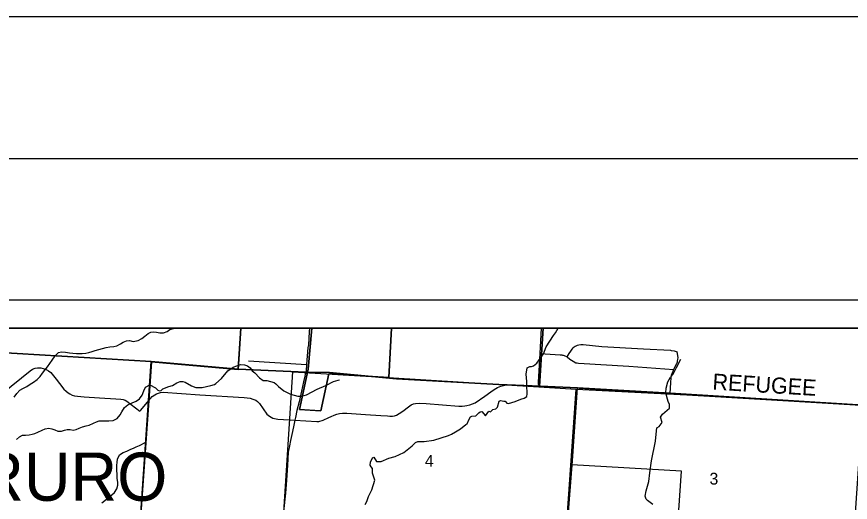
# Model space of a CAD drawing. Extents: x 0 to 34, y 0 to 22.
# Drawn here: x 3.515 to 6.46, y 20.286 to 22 of the extents above; entities that cross this region are included whole.
import ezdxf

# ---------------------------------------------------------------- set-up
doc = ezdxf.new("R2010")
doc.units = 0
for name, color, linetype in [('GM_X_City_Street', 7, 'Continuous'), ('GM_X_Corporation', 7, 'Continuous'), ('GM_X_County', 7, 'Continuous'), ('GM_X_Minor_River', 7, 'Continuous'), ('GM_X_Section_Text', 7, 'Continuous'), ('GM_X_Township_Road', 7, 'Continuous'), ('GM_X_Township_Road_Text', 7, 'Continuous'), ('GM_X_Township_Text', 7, 'Continuous'), ('SH_Border', 7, 'Continuous'), ('SH_Cut_Line', 7, 'Continuous'), ('SH_Data', 7, 'Continuous')]:
    doc.layers.add(name, color=color, linetype=linetype)

msp = doc.modelspace()

# ---------------------------------------------------------------- linework, layer by layer
at = {"layer": 'GM_X_City_Street'}
msp.add_line((4.3347, 20.7849), (4.539, 20.7724), dxfattribs=at)
for points in [[(5.4597, 20.7994), (5.4672, 20.8117), (5.4721, 20.8193), (5.4774, 20.8266), (5.4804, 20.8308), (5.485, 20.8342), (5.488, 20.8369), (5.491, 20.8384), (5.4959, 20.8407), (5.5009, 20.8422), (5.5077, 20.8427), (5.5168, 20.8427), (5.5821, 20.8358), (5.7294, 20.8277), (5.8244, 20.8231), (5.827, 20.822), (5.838, 20.8202), (5.8487, 20.8175)], [(5.824, 20.6706), (5.8262, 20.7075), (5.8275, 20.7265), (5.8287, 20.7351), (5.836, 20.7547), (5.8364, 20.756), (5.8466, 20.7757), (5.8477, 20.778), (5.8492, 20.7822), (5.8499, 20.7856), (5.8507, 20.7898), (5.8514, 20.7974), (5.8487, 20.8175)], [(5.3643, 20.8113), (5.435, 20.8066), (5.4388, 20.8063), (5.4407, 20.8063), (5.4433, 20.8055), (5.446, 20.8052), (5.4494, 20.8037), (5.4597, 20.7994), (5.4691, 20.7906), (5.4805, 20.784), (5.4905, 20.7784), (5.4935, 20.778), (5.4951, 20.7776), (5.5, 20.7769), (5.6773, 20.7663), (5.836, 20.7547)], [(4.4984, 20.5754), (4.576, 20.571), (4.5831, 20.5714), (4.5984, 20.5762), (4.6175, 20.585), (4.6262, 20.5889), (4.6365, 20.593), (4.6464, 20.5971), (4.6555, 20.5996), (4.6663, 20.6009), (4.6816, 20.6004), (4.7477, 20.5963), (4.8018, 20.5918), (4.8246, 20.5909), (4.8337, 20.5905), (4.8423, 20.5905), (4.8502, 20.5913), (4.8572, 20.5938), (4.8663, 20.5988), (4.8795, 20.6071), (4.8998, 20.6232), (4.9089, 20.6294), (4.9168, 20.6331), (4.9242, 20.6352), (4.9391, 20.636), (4.9614, 20.6347), (5.0193, 20.6294), (5.0771, 20.6252), (5.0892, 20.6253), (5.0978, 20.6259), (5.1059, 20.6272), (5.1164, 20.6302), (5.1252, 20.6332), (5.1342, 20.6373), (5.1685, 20.6606), (5.1899, 20.6756), (5.2018, 20.6841), (5.2134, 20.6916), (5.2256, 20.6963), (5.2399, 20.6998), (5.2476, 20.7), (5.3655, 20.695)], [(3.9816, 20.645), (3.9939, 20.6591), (4.0028, 20.6649), (4.0089, 20.6689), (4.0232, 20.6731), (4.0323, 20.6743), (4.1624, 20.6651), (4.3187, 20.6553), (4.3396, 20.6533), (4.3499, 20.6504), (4.3597, 20.6466), (4.3664, 20.6418), (4.3734, 20.6349), (4.3985, 20.5973), (4.4085, 20.5894), (4.4196, 20.5831), (4.438, 20.5789), (4.4984, 20.5754)]]:
    msp.add_lwpolyline(points, dxfattribs=at)
at = {"layer": 'GM_X_Corporation'}
for points in [[(4.3071, 20.9), (2.1, 20.9), (2.1, 14.1), (3.0169, 14.1), (3.0406, 14.4484), (3.1026, 15.287), (3.1745, 16.2606), (2.934, 16.2765), (2.366, 16.3159), (2.2862, 16.3208), (2.1768, 16.323), (2.2478, 17.3472), (2.3155, 18.3567), (3.8153, 18.2543), (3.8503, 18.7566), (3.8611, 18.9124), (3.8924, 19.3621), (3.9019, 19.4987), (3.9133, 19.6628), (3.9816, 20.645), (3.9912, 20.7822), (4.2975, 20.7549)], [(4.3068, 20.9), (2.1, 20.9), (2.1, 20.8993), (2.2596, 20.8916), (2.7336, 20.8606), (3.2798, 20.8248), (3.9909, 20.7828), (4.2973, 20.7554)], [(8.9, 20.4724), (8.9, 20.9), (4.3068, 20.9), (4.2973, 20.7554), (4.5367, 20.7456), (4.6201, 20.7441), (4.8574, 20.7216), (5.2396, 20.7003), (5.2473, 20.7005), (5.3653, 20.6955), (5.4957, 20.69), (5.8237, 20.6711), (6.676, 20.6183), (7.8827, 20.5405), (8.4655, 20.5021), (8.5224, 20.4984)], [(4.8398, 20.9), (4.5578, 20.9), (4.5447, 20.7555), (4.5144, 20.614), (4.5896, 20.6089), (4.6184, 20.7391), (4.8298, 20.7264)], [(8.9, 20.4697), (8.9, 20.9), (5.3755, 20.9), (5.362, 20.6955), (5.3653, 20.6955), (5.4957, 20.69), (5.5024, 20.6884), (6.6719, 20.618), (7.8826, 20.5367), (8.4626, 20.4977), (8.5169, 20.4922)], [(4.4912, 20.7461), (4.8271, 20.7263), (5.3592, 20.6938), (5.4919, 20.6855), (5.4537, 20.1473), (4.9568, 20.181), (4.9537, 20.1812), (4.4572, 20.2143)], [(5.4919, 20.6855), (5.8824, 20.6656), (6.3999, 20.6351), (6.5029, 20.629), (6.4654, 20.076), (5.9674, 20.1102), (5.4537, 20.1473)]]:
    msp.add_lwpolyline(points, close=True, dxfattribs=at)
for points in [[(3.8151, 18.2549), (3.8501, 18.7572), (3.8609, 18.9129), (3.8918, 19.3576), (3.8924, 19.3656), (3.9015, 19.4967), (3.9015, 19.497), (3.9131, 19.6633), (3.9131, 19.6638), (3.9335, 19.9563), (3.9417, 20.0742), (3.9814, 20.6455), (3.9909, 20.7828), (4.2973, 20.7554), (4.3068, 20.9), (2.1, 20.9), (2.1, 14.1)], [(3.8151, 18.2549), (3.8501, 18.7572), (3.8609, 18.9129), (3.8918, 19.3576), (3.8924, 19.3656), (3.9015, 19.4967), (3.9015, 19.497), (3.9131, 19.6633), (3.9131, 19.6638), (3.9335, 19.9563), (3.9417, 20.0742), (3.9814, 20.6455), (3.9909, 20.7828), (3.2798, 20.8248), (2.7336, 20.8606), (2.2596, 20.8916), (2.1, 20.8993), (2.1, 16.3272)], [(5.8451, 20.1209), (5.864, 20.3961), (5.4765, 20.4182), (5.4847, 20.546), (5.4957, 20.69), (5.3653, 20.6955), (5.362, 20.6955), (5.3755, 20.9), (4.8398, 20.9), (4.8298, 20.7264), (4.6184, 20.7391), (4.5896, 20.6089), (4.5863, 20.6092), (4.5144, 20.614), (4.5447, 20.7555), (4.5578, 20.9), (2.7432, 20.9)], [(8.9, 20.9), (4.3068, 20.9), (4.2973, 20.7554), (3.9909, 20.7828), (3.9814, 20.6455), (3.9417, 20.0742), (3.9335, 19.9563), (3.9131, 19.6638), (3.9131, 19.6633), (3.9015, 19.497), (3.9015, 19.4967), (3.8924, 19.3656), (3.8918, 19.3576), (3.8609, 18.9129), (3.8501, 18.7572), (3.8151, 18.2549)], [(8.9, 20.9), (4.3071, 20.9), (4.2975, 20.7549), (3.9912, 20.7822), (3.9816, 20.645), (3.9133, 19.6628), (3.9019, 19.4987), (3.8924, 19.3621), (3.8611, 18.9124), (3.8503, 18.7566), (3.8153, 18.2543), (4.1999, 18.2271), (4.3271, 18.2226), (4.5528, 18.2021), (4.7449, 18.1929), (4.9551, 18.1768), (5.5447, 18.1318), (5.8371, 18.1158), (5.9465, 18.1082), (6.0343, 18.1015), (6.0906, 18.0978), (6.5646, 18.0583)], [(6.676, 20.6183), (5.8237, 20.6711), (5.4957, 20.69), (5.3653, 20.6955), (5.2473, 20.7005), (5.2396, 20.7003), (4.8574, 20.7216), (4.6201, 20.7441), (4.5367, 20.7456), (4.2973, 20.7554), (3.9909, 20.7828), (3.9814, 20.6455), (3.9417, 20.0742), (3.9335, 19.9563), (3.9131, 19.6638), (3.9131, 19.6633), (3.9015, 19.497), (3.9015, 19.4967), (3.8924, 19.3656), (3.8918, 19.3576), (3.8609, 18.9129), (3.8501, 18.7572), (3.8151, 18.2549)]]:
    msp.add_lwpolyline(points, dxfattribs=at)
at = {"layer": 'GM_X_County'}
msp.add_lwpolyline([(3.8151, 18.2549), (3.8501, 18.7572), (3.8609, 18.9129), (3.8918, 19.3576), (3.8924, 19.3656), (3.9015, 19.4967), (3.9015, 19.497), (3.9131, 19.6633), (3.9131, 19.6638), (3.9335, 19.9563), (3.9417, 20.0742), (3.9814, 20.6455), (3.9909, 20.7828), (4.2973, 20.7554), (4.3068, 20.9)], dxfattribs=at)
at = {"layer": 'GM_X_Minor_River'}
for points in [[(3.5063, 20.6574), (3.5158, 20.6703), (3.5261, 20.6812), (3.5375, 20.688), (3.5515, 20.6943), (3.5633, 20.7026), (3.575, 20.7098), (3.5872, 20.7195), (3.5978, 20.7301), (3.607, 20.7422), (3.6146, 20.752), (3.6238, 20.7641), (3.6322, 20.7754), (3.6409, 20.7875), (3.6512, 20.803), (3.6634, 20.8147), (3.674, 20.8169), (3.6884, 20.8157), (3.7024, 20.8133), (3.7137, 20.8125), (3.7265, 20.8109), (3.7368, 20.8109), (3.7473, 20.8112), (3.7594, 20.8122), (3.77, 20.8144), (3.7818, 20.8178), (3.7928, 20.8219), (3.8053, 20.8256), (3.8189, 20.8293), (3.831, 20.8323), (3.8443, 20.8341), (3.859, 20.8359), (3.8693, 20.8385), (3.8818, 20.8453), (3.892, 20.8513), (3.9034, 20.8558), (3.9144, 20.8572), (3.9268, 20.8537), (3.9443, 20.8566), (3.9575, 20.8638), (3.9682, 20.8721), (3.9796, 20.8815), (3.9894, 20.886), (3.9997, 20.8878), (4.0095, 20.8862), (4.0212, 20.8835), (4.0341, 20.8846), (4.0466, 20.889), (4.0568, 20.8958), (4.0689, 20.8995), (4.0702, 20.9)], [(5.123, 20.5903), (5.137, 20.5911), (5.1476, 20.6013), (5.1525, 20.6055), (5.1586, 20.6066), (5.1707, 20.5906), (5.1836, 20.6081), (5.1885, 20.6054), (5.1972, 20.6138), (5.2078, 20.6156), (5.2135, 20.6221), (5.2195, 20.6429), (5.2248, 20.6448), (5.2301, 20.6441), (5.2362, 20.6429), (5.2411, 20.6425), (5.2468, 20.6357), (5.2521, 20.6346), (5.2759, 20.6417), (5.296, 20.6504), (5.3073, 20.6531), (5.3168, 20.6595), (5.3187, 20.6683), (5.318, 20.6789), (5.3168, 20.6887), (5.3172, 20.7126), (5.315, 20.7385), (5.3188, 20.7601), (5.3279, 20.7658), (5.3332, 20.7654), (5.3412, 20.7676), (5.3521, 20.7771), (5.376, 20.8101), (5.3855, 20.8344), (5.4117, 20.8746), (5.4181, 20.884), (5.4275, 20.9)], [(5.7619, 20.2784), (5.743, 20.2925), (5.7389, 20.2974), (5.7355, 20.308), (5.7382, 20.3266), (5.7485, 20.3589), (5.7516, 20.3904), (5.7581, 20.4317), (5.7722, 20.5011), (5.7757, 20.5387), (5.7765, 20.5486), (5.7845, 20.5539), (5.7951, 20.5675), (5.7894, 20.5865), (5.7959, 20.5967), (5.8206, 20.6183), (5.8217, 20.6244), (5.821, 20.6312), (5.8168, 20.6415), (5.8138, 20.6498), (5.8078, 20.6719), (5.809, 20.6886), (5.8151, 20.7117), (5.8246, 20.7272), (5.8337, 20.7386), (5.8455, 20.7614), (5.8607, 20.7917)], [(3.9862, 20.7007), (4.0052, 20.6899), (4.0142, 20.6812), (4.0195, 20.6789), (4.0252, 20.6808), (4.0317, 20.6861), (4.0525, 20.6948), (4.0653, 20.6978), (4.0805, 20.7073), (4.0934, 20.7122), (4.1017, 20.7126), (4.11, 20.7099), (4.1327, 20.6966), (4.1478, 20.6913), (4.1709, 20.6913), (4.2015, 20.698), (4.2137, 20.7022), (4.2186, 20.7049), (4.239, 20.7227), (4.261, 20.7503), (4.2796, 20.7632), (4.3064, 20.7727), (4.3201, 20.7711), (4.3306, 20.7673), (4.3401, 20.7605), (4.3476, 20.7499), (4.3567, 20.7423), (4.3726, 20.7248), (4.3858, 20.7153), (4.3987, 20.7153), (4.4251, 20.7088), (4.4312, 20.7046), (4.4406, 20.6947), (4.4592, 20.6795), (4.483, 20.6674), (4.5087, 20.6605), (4.5231, 20.6605), (4.539, 20.6654), (4.5772, 20.6855), (4.6071, 20.6976), (4.6347, 20.7123), (4.6506, 20.7169), (4.6556, 20.718)], [(3.5152, 20.5079), (3.5251, 20.5165), (3.5361, 20.5225), (3.5463, 20.5232), (3.5595, 20.5239), (3.5701, 20.5261), (3.5796, 20.5287), (3.5906, 20.5332), (3.6054, 20.5403), (3.6164, 20.5448), (3.6285, 20.547), (3.6398, 20.5454), (3.6496, 20.5412), (3.6606, 20.5373), (3.6742, 20.5369), (3.6844, 20.5402), (3.6943, 20.5432), (3.7041, 20.5424), (3.7147, 20.5404), (3.7253, 20.5423), (3.7366, 20.5479), (3.7484, 20.552), (3.7605, 20.5553), (3.7711, 20.5583), (3.7863, 20.5647), (3.7969, 20.5699), (3.8068, 20.5733), (3.8181, 20.5736), (3.8306, 20.5731), (3.8408, 20.573), (3.8567, 20.5752), (3.8707, 20.5816), (3.8806, 20.5952), (3.8864, 20.6058), (3.8959, 20.6201), (3.9081, 20.6303), (3.9236, 20.6374), (3.938, 20.643), (3.9494, 20.6506), (3.959, 20.6645), (3.9643, 20.6793), (3.9705, 20.6918), (3.9862, 20.7007)], [(4.7458, 20.2781), (4.7526, 20.2891), (4.7583, 20.3058), (4.7693, 20.3297), (4.78, 20.3642), (4.7724, 20.3889), (4.7717, 20.4048), (4.7675, 20.4109), (4.7645, 20.4173), (4.7649, 20.428), (4.7717, 20.4427), (4.777, 20.445), (4.7861, 20.4298), (4.8027, 20.4294), (4.83, 20.4412), (4.8519, 20.4476), (4.8826, 20.462), (4.9121, 20.4847), (4.9235, 20.4972), (4.9318, 20.501), (4.9432, 20.5002), (4.9542, 20.501), (4.989, 20.5055), (5.0408, 20.5214), (5.0514, 20.5259), (5.0651, 20.5342), (5.0832, 20.5452), (5.1014, 20.5611), (5.1071, 20.5626), (5.112, 20.5771), (5.1181, 20.5873), (5.123, 20.5903)], [(3.8167, 20.2837), (3.827, 20.2927), (3.8395, 20.3033), (3.8517, 20.3123), (3.8615, 20.3209), (3.8696, 20.3334), (3.8727, 20.3467), (3.8727, 20.3566), (3.8709, 20.3702), (3.8699, 20.3805), (3.8692, 20.4025), (3.8693, 20.4154), (3.8701, 20.4275), (3.8717, 20.4381), (3.8786, 20.4537), (3.8919, 20.4619), (3.904, 20.4668), (3.9181, 20.4735), (3.9276, 20.4773), (3.9374, 20.4814), (3.9495, 20.4862), (3.9721, 20.4977)]]:
    msp.add_lwpolyline(points, dxfattribs=at)
at = {"layer": 'GM_X_Township_Road'}
msp.add_line((5.4959, 20.6894), (5.3655, 20.695), dxfattribs=at)
for points in [[(4.55, 20.9), (4.5488, 20.8881), (4.5459, 20.8415), (4.5439, 20.8328), (4.539, 20.7724), (4.5389, 20.771), (4.5375, 20.7516), (4.5369, 20.7451), (4.5362, 20.7424)], [(5.3655, 20.695), (5.3619, 20.6984), (5.359, 20.7032), (5.3579, 20.7103), (5.3643, 20.8113), (5.3695, 20.9)], [(3.465, 20.6714), (3.5625, 20.7503), (3.5716, 20.7558), (3.5812, 20.7594), (3.5885, 20.7602), (3.5951, 20.7603), (3.6008, 20.7601), (3.6094, 20.7587), (3.6196, 20.7549), (3.6281, 20.75), (3.636, 20.7435), (3.6452, 20.7327), (3.6546, 20.7201), (3.6663, 20.7047), (3.6822, 20.6847), (3.6898, 20.6779), (3.6971, 20.6725), (3.703, 20.6682), (3.7117, 20.6642), (3.7202, 20.662), (3.7302, 20.6602), (3.7534, 20.6582), (3.8084, 20.6544), (3.8654, 20.6509), (3.8832, 20.6497), (3.8915, 20.6483), (3.8991, 20.6461), (3.9049, 20.6432), (3.9508, 20.6074), (3.9539, 20.6109), (3.9816, 20.645)], [(4.5362, 20.7424), (4.5347, 20.737), (4.5335, 20.7312), (4.5283, 20.7115), (4.5251, 20.6945), (4.5211, 20.6778), (4.5127, 20.6403), (4.5055, 20.6101), (4.5006, 20.5847), (4.4984, 20.5754), (4.4942, 20.5586), (4.4898, 20.5362), (4.4825, 20.5041), (4.4789, 20.4855), (4.4748, 20.4628), (4.4716, 20.4165), (4.4686, 20.3638), (4.465, 20.3179), (4.4581, 20.2538), (4.455, 20.2117), (4.4534, 20.181)], [(5.4565, 20.146), (5.4788, 20.4326), (5.4959, 20.6894)], [(6.6762, 20.6178), (5.824, 20.6706), (5.4959, 20.6894)]]:
    msp.add_lwpolyline(points, dxfattribs=at)
at = {"layer": 'SH_Border'}
msp.add_lwpolyline([(1.5, 21.5), (33.5, 21.5), (33.5, 0.5), (1.5, 0.5)], close=True, dxfattribs=at)
at = {"layer": 'SH_Cut_Line'}
msp.add_lwpolyline([(0, 0), (34, 0), (34, 22), (0, 22)], close=True, dxfattribs=at)
at = {"layer": 'SH_Data'}
for p, q in [((2, 21), (9, 21)), ((2.1, 20.9), (8.9, 20.9))]:
    msp.add_line(p, q, dxfattribs=at)

# ---------------------------------------------------------------- texts
at = {"layer": 'GM_X_Section_Text'}
for s, p in [('4', (4.957, 20.4112)), ('3', (5.9624, 20.3484))]:
    msp.add_text(s, height=0.0419, rotation=0, dxfattribs=at).set_placement(p)
at = {"layer": 'GM_X_Township_Road_Text'}
msp.add_text('REFUGEE', height=0.05682, rotation=356.4805, dxfattribs=at).set_placement((5.9717, 20.684))
at = {"layer": 'GM_X_Township_Text'}
msp.add_text('TRURO', height=0.17045, rotation=0, dxfattribs=at).set_placement((3.2372, 20.2911))

doc.saveas('drawing.dxf')
